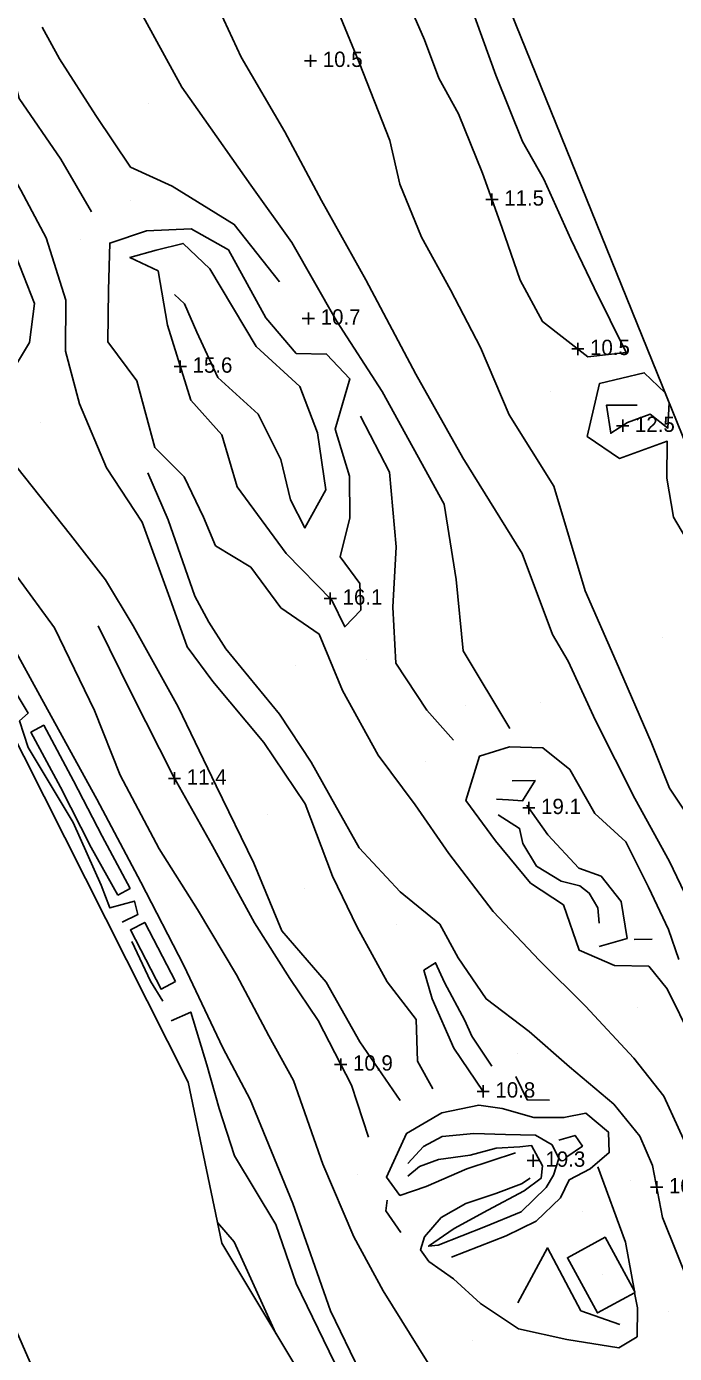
# Model space of a CAD drawing. Extents: x 2316231 to 2323598, y 363169 to 371906.
# Drawn here: x 2321145.5 to 2321357, y 370235.9 to 370669.2 of the extents above; entities that cross this region are included whole.
import ezdxf

# ---------------------------------------------------------------- set-up
doc = ezdxf.new("R2010")
doc.units = 0
for name, color, linetype in [('RD_DTM_BkLn1', 7, 'Continuous'), ('RD_DTM_Holes', 7, 'Continuous'), ('RD_DTM_Spot', 7, 'Continuous'), ('RD_DTM_TinHull', 7, 'Continuous'), ('RD_DTM_Void', 7, 'Continuous'), ('RD_EX_Road', 7, 'Continuous')]:
    doc.layers.add(name, color=color, linetype=linetype)

msp = doc.modelspace()

# ---------------------------------------------------------------- linework, layer by layer
at = {"layer": 'RD_DTM_BkLn1'}
for p, q in [((2321303.283, 370439.966), (2321287.994, 370465.333)), ((2321343.823, 370371.073), (2321349.76, 370371.225))]:
    msp.add_line(p, q, dxfattribs=at)
for points in [[(2321095.104, 370838.549), (2321106.9, 370830.963), (2321120.13, 370820.522), (2321134.171, 370806.445), (2321148.563, 370787.326), (2321155.431, 370774.673), (2321167.88, 370758.44), (2321178.411, 370739.764), (2321191.256, 370710.961), (2321204.225, 370683.754), (2321215.503, 370659.267), (2321229.851, 370634.787), (2321241.736, 370612.469), (2321256.273, 370586.516), (2321272.543, 370555.7), (2321287.931, 370528.428), (2321307.356, 370497.108), (2321317.191, 370470.678)], [(2321166.692, 370608.729), (2321156.687, 370625.95), (2321143.02, 370645.697), (2321139.377, 370659.675), (2321129.348, 370678.61), (2321116.078, 370701.328), (2321100.407, 370726.439), (2321084.462, 370753.707), (2321065.004, 370781.518), (2321049.856, 370800.449), (2321028.316, 370822.126), (2321001.341, 370834.458), (2320980.791, 370835.833)], [(2321154.64, 370472.869), (2321142.488, 370489.377), (2321128.682, 370513.676), (2321120.144, 370529.674), (2321109.083, 370544.963), (2321095.862, 370565.132), (2321084.807, 370586.293), (2321069.264, 370611.437), (2321056.818, 370634.294), (2321042.259, 370659.391), (2321027.715, 370688.401)], [(2321290.025, 370677.374), (2321298.704, 370653.383), (2321307.435, 370631.662), (2321314.33, 370619.356), (2321323.183, 370599.834), (2321330.83, 370583.917), (2321341.307, 370562.798), (2321328.747, 370561.407), (2321313.932, 370572.9), (2321306.601, 370586.427), (2321300.661, 370603.689), (2321294.368, 370621.361), (2321286.521, 370640.708), (2321280.081, 370652.371), (2321275.447, 370664.88), (2321267.471, 370683.198)], [(2321287.994, 370465.333), (2321285.707, 370488.607), (2321281.842, 370513.208), (2321261.585, 370550.085), (2321246.64, 370573.114), (2321232.11, 370598.708), (2321218.661, 370617.432), (2321201.444, 370642.041), (2321196.129, 370649.382), (2321181.681, 370675.913)], [(2321245.723, 370677.826), (2321254.102, 370657.475), (2321264.116, 370631.962), (2321267.396, 370617.699), (2321274.413, 370600.435), (2321283.909, 370583.244), (2321293.731, 370564.392), (2321303.026, 370542.421), (2321317.678, 370519.106), (2321327.827, 370484.903)], [(2321197.855, 370466.624), (2321192.255, 370482.578), (2321183.216, 370507.361), (2321171.573, 370525.124), (2321162.727, 370546.059), (2321158.187, 370563.164), (2321158.297, 370579.874), (2321151.818, 370600.223), (2321143.586, 370615.777), (2321131.818, 370636.402), (2321122.85, 370656.783), (2321113.172, 370672.46)], [(2321228.111, 370585.812), (2321213.298, 370604.623), (2321193.006, 370617.066), (2321179.443, 370623.25), (2321168.114, 370640.187), (2321156.203, 370658.672), (2321150.546, 370669.063)], [(2321241.043, 370470.832), (2321228.497, 370479.45), (2321218.754, 370492.673), (2321207.159, 370499.689), (2321203.213, 370508.969), (2321196.943, 370522.182), (2321187.395, 370531.708), (2321181.468, 370553.555), (2321172.043, 370566.299), (2321172.201, 370583.181), (2321172.641, 370598.508), (2321184.678, 370602.5), (2321199.174, 370603.171), (2321211.362, 370596.345), (2321223.607, 370574.138), (2321233.521, 370562.465), (2321243.432, 370562.292), (2321251.03, 370554.204), (2321246.268, 370537.751), (2321250.877, 370522.417), (2321251.062, 370508.842), (2321247.818, 370496.076), (2321254.307, 370487.307), (2321254.578, 370478.653), (2321249.367, 370473.219), (2321245.159, 370481.924), (2321230.218, 370497.135), (2321214.25, 370518.949), (2321209.186, 370535.875), (2321199.083, 370547.25), (2321191.463, 370571.69), (2321188.413, 370589.447), (2321179.193, 370593.804), (2321187.736, 370596.219), (2321196.6, 370598.398), (2321205.352, 370590.087), (2321220.442, 370564.787), (2321234.703, 370551.669), (2321240.463, 370536.598), (2321243.142, 370517.942), (2321236.347, 370505.522), (2321231.671, 370514.719), (2321228.492, 370527.857), (2321221.073, 370542.602), (2321207.931, 370554.571), (2321201.012, 370569.46), (2321197.042, 370578.682), (2321193.723, 370581.759)], [(2321140.891, 370597.039), (2321148.08, 370578.731), (2321146.423, 370566.002), (2321139.37, 370554.245)], [(2321363.467, 370497.534), (2321356.737, 370508.982), (2321354.515, 370521.761), (2321354.658, 370533.78), (2321339.103, 370528.201), (2321328.575, 370535.353), (2321332.549, 370552.65), (2321347.174, 370556.169), (2321354.016, 370549.609)], [(2321355.283, 370546.482), (2321354.91, 370538.096), (2321349.144, 370542.687), (2321341.754, 370539.886), (2321336.255, 370536.413), (2321334.856, 370545.614), (2321344.85, 370545.637)], [(2321266.031, 370461.336), (2321265.059, 370479.596), (2321266.192, 370499.349), (2321263.946, 370523.744), (2321254.533, 370541.988)], [(2321180.251, 370473.577), (2321171.221, 370488.569), (2321159.769, 370503.203), (2321142.254, 370525.384)], [(2321204.999, 370474.705), (2321200.382, 370483.25), (2321191.668, 370508.144), (2321185.031, 370523.435)], [(2321462.422, 370192.436), (2321464.032, 370206.907), (2321452.063, 370233.225), (2321443.112, 370248.747), (2321437.452, 370259.196), (2321435.091, 370275.485), (2321426.405, 370297.189), (2321414.04, 370318.191), (2321404.119, 370337.788), (2321394.56, 370357.878), (2321382.23, 370381.657), (2321370.16, 370398.51), (2321355.45, 370420.524), (2321349.442, 370435.572), (2321337.968, 370461.876), (2321327.827, 370484.903)], [(2321176.646, 370376.75), (2321181.841, 370379.299), (2321180.704, 370383.666), (2321172.667, 370381.401), (2321169.802, 370388.856), (2321160.706, 370409.303), (2321145.975, 370433.825), (2321143.173, 370442.55), (2321145.961, 370445.01), (2321137.174, 370459.689), (2321126.274, 370479.167)], [(2321373.342, 370054.777), (2321358.045, 370085.574), (2321345.881, 370110.926), (2321329.281, 370134.816), (2321317.006, 370155.874), (2321302.796, 370181.337), (2321289.265, 370207.662), (2321276.571, 370232.77), (2321261.937, 370256.391), (2321252.287, 370273.963), (2321242.184, 370297.777), (2321232.592, 370325.072), (2321224.625, 370339.623), (2321214.019, 370359.55), (2321201.24, 370380.869), (2321188.745, 370400.714), (2321176.047, 370424.799), (2321167.639, 370445.883), (2321154.64, 370472.869)], [(2321257.177, 370306.517), (2321251.526, 370323.519), (2321240.69, 370344.616), (2321231.381, 370358.341), (2321219.846, 370376.586), (2321206.174, 370401.698), (2321193.435, 370424.299), (2321179.794, 370451.231), (2321168.829, 370473.509)], [(2321267.476, 370318.496), (2321254.315, 370337.726), (2321243.258, 370357.194), (2321228.781, 370373.923), (2321219.693, 370395.978), (2321207.393, 370421.241), (2321195.018, 370447.055), (2321180.251, 370473.577)], [(2321406.892, 370255.712), (2321389.176, 370248.986), (2321375.672, 370248.197), (2321362.506, 370257.074), (2321353.097, 370280.277), (2321349.908, 370297.255), (2321345.727, 370306.876), (2321337.201, 370317.349), (2321322.792, 370329.492), (2321309.583, 370341.09), (2321295.526, 370351.68), (2321286.418, 370365.078), (2321280.401, 370376.057), (2321267.48, 370386.641), (2321254.059, 370400.994), (2321246.102, 370415.152), (2321238.378, 370429.027), (2321228.112, 370444.646), (2321210.578, 370466.034), (2321204.999, 370474.705)], [(2321362.947, 370299.429), (2321353.536, 370319.957), (2321343.715, 370332.314), (2321327.947, 370349.342), (2321312.933, 370364.231), (2321297.812, 370380.289), (2321283.368, 370399.188), (2321272.316, 370415.025), (2321260.332, 370431.271), (2321248.609, 370452.371), (2321241.043, 370470.832)], [(2321361.5, 370383.803), (2321355.413, 370396.614), (2321344.069, 370417.117), (2321331.253, 370442.562), (2321322.365, 370461.94), (2321317.191, 370470.678)], [(2321278.185, 370322.345), (2321273.103, 370331.362), (2321272.73, 370344.955), (2321263.246, 370357.277), (2321253.383, 370375.108), (2321245.415, 370391.762), (2321236.401, 370415.39), (2321222.952, 370435.442), (2321206.277, 370455.375), (2321197.855, 370466.624)], [(2321284.896, 370436.165), (2321276.153, 370446.033), (2321266.031, 370461.336)], [(2321358.473, 370364.528), (2321355.092, 370374.313), (2321348.549, 370388.194), (2321341.19, 370403.034), (2321331.061, 370412.211), (2321322.823, 370426.606), (2321314.056, 370433.731), (2321303.153, 370433.986), (2321293.369, 370430.92), (2321288.893, 370416.462), (2321298.609, 370403.33), (2321309.986, 370389.504), (2321320.822, 370382.392), (2321325.877, 370367.586), (2321337.499, 370362.639), (2321348.66, 370362.417), (2321354.605, 370354.991), (2321362.832, 370338.415)], [(2321298.911, 370416.908), (2321302.856, 370416.721), (2321307.418, 370416.406), (2321311.52, 370422.985), (2321304.078, 370422.954)], [(2321332.439, 370376.378), (2321331.992, 370381.473), (2321329.227, 370386.23), (2321326.113, 370388.651), (2321319.994, 370390.187), (2321311.935, 370395.093), (2321307.486, 370402.467), (2321306.464, 370407.384), (2321299.414, 370411.769)], [(2321308.828, 370414.983), (2321315.649, 370405.294), (2321325.793, 370394.419), (2321333.064, 370391.731), (2321339.589, 370383.516), (2321341.555, 370371.444), (2321332.414, 370368.779)], [(2321179.875, 370370.394), (2321185.985, 370357.538), (2321189.955, 370350.999)], [(2321294.56, 370321.479), (2321285.017, 370335.61), (2321277.889, 370351.675), (2321275.213, 370361.03), (2321279.048, 370363.507), (2321281.894, 370357.018), (2321288.601, 370344.597), (2321290.848, 370339.573), (2321297.388, 370329.772)], [(2321257.719, 370204.746), (2321249.591, 370225.56), (2321233.496, 370258.766), (2321226.834, 370278.021), (2321213.317, 370300.434), (2321208.401, 370315.915), (2321204.378, 370330.177), (2321199.099, 370347.391), (2321192.644, 370344.488)], [(2321316.186, 370318.609), (2321308.891, 370318.756), (2321305.195, 370326.396)], [(2321284.192, 370267.368), (2321302.032, 370274.296), (2321311.914, 370279.082), (2321319.82, 370286.789), (2321322.692, 370292.632), (2321329.488, 370296.23), (2321335.742, 370301.494), (2321335.448, 370308.218), (2321328.047, 370314.369), (2321320.925, 370312.954), (2321311.145, 370313.001), (2321300.738, 370315.952), (2321293.133, 370316.978)], [(2321270.021, 370293.775), (2321273.746, 370296.972), (2321279.962, 370299.258), (2321290.299, 370300.624), (2321298.821, 370302.966), (2321306.523, 370303.401), (2321310.381, 370303.82), (2321313.923, 370297.171), (2321313.465, 370293.126), (2321307.96, 370288.994), (2321296.114, 370282.666), (2321285.08, 370276.75), (2321276.745, 370270.945), (2321279.905, 370271.267), (2321295.302, 370277.409), (2321307.027, 370282.118), (2321315.182, 370290.06), (2321317.562, 370294.129), (2321319.275, 370299.573), (2321317.138, 370304.035), (2321311.679, 370307.209), (2321301.866, 370307.425), (2321291.503, 370307.756), (2321281.167, 370306.761), (2321275.093, 370303.53), (2321270.018, 370297.99)], [(2321321.908, 370300.078), (2321326.984, 370303.639), (2321324.561, 370307.102), (2321319.27, 370305.599)], [(2321267.706, 370275.429), (2321262.805, 370282.445), (2321263.261, 370285.995)], [(2321226.864, 370242.463), (2321224.094, 370248.447), (2321213.238, 370272.41), (2321207.768, 370278.66)], [(2321339.191, 370245.428), (2321326.51, 370249.862), (2321315.536, 370270.397), (2321305.861, 370252.458)]]:
    msp.add_lwpolyline(points, dxfattribs=at)
at = {"layer": 'RD_DTM_Holes'}
msp.add_lwpolyline([(2321261.802, 370184.289), (2321209.177, 370271.912), (2321198.19, 370324.497), (2321117.576, 370484.29), (2321037.89, 370459.753), (2321124.606, 370283.08), (2321175.43, 370167.171)], dxfattribs=at)
at = {"layer": 'RD_DTM_Spot'}
for p, q in [((2321185.317, 370644.252), (2321185.317, 370644.252)), ((2321179.337, 370612.273), (2321179.337, 370612.273)), ((2321163.077, 370599.557), (2321163.077, 370599.557)), ((2321237.501, 370573.891), (2321237.501, 370573.891)), ((2321316.532, 370549.902), (2321316.532, 370549.902)), ((2321150.061, 370539.968), (2321150.061, 370539.968)), ((2321353.192, 370469.559), (2321353.192, 370469.559)), ((2321233.283, 370460.721), (2321233.283, 370460.721)), ((2321256.582, 370462.426), (2321256.582, 370462.426)), ((2321288.695, 370447.579), (2321288.695, 370447.579)), ((2321313.374, 370448.506), (2321313.374, 370448.506)), ((2321275.734, 370429.116), (2321275.734, 370429.116)), ((2321319.258, 370416.911), (2321319.258, 370416.911)), ((2321224.008, 370411.987), (2321224.008, 370411.987)), ((2321236.279, 370387.804), (2321236.279, 370387.804)), ((2321266.135, 370375.867), (2321266.135, 370375.867)), ((2321345.054, 370348.821), (2321345.054, 370348.821)), ((2321305.872, 370333.744), (2321305.872, 370333.744)), ((2321253.554, 370294.237), (2321253.554, 370294.237)), ((2321342.667, 370292.333), (2321342.667, 370292.333)), ((2321326.959, 370282.359), (2321326.959, 370282.359)), ((2321333.458, 370261.666), (2321333.458, 370261.666)), ((2321355.174, 370249.589), (2321355.174, 370249.589)), ((2321291.132, 370240.31), (2321291.132, 370240.31))]:
    msp.add_line(p, q, dxfattribs=at)
at = {"layer": 'RD_DTM_TinHull'}
msp.add_lwpolyline([(2319782.271, 371232.132), (2319735.05, 371773.026), (2320925.274, 371905.831), (2321343.399, 371858.015), (2321109.741, 371125.092), (2321259.088, 370783.878), (2321451.866, 370308.131), (2321545.882, 369878.312), (2321496.483, 369600.925), (2321592.742, 369376.322), (2321772.553, 369180.585), (2321930.831, 369046.826), (2322410.389, 369187.058), (2322700.489, 369322.074), (2323031.423, 369488.086), (2323384.71, 369626.658), (2323598.112, 369182.404), (2323506.079, 369141.824), (2322749.057, 368805.183), (2322437.788, 368637.943)], dxfattribs=at)
at = {"layer": 'RD_DTM_Void'}
for p, q in [((2321238.197, 370656.027), (2321238.197, 370660.027)), ((2321236.197, 370658.027), (2321240.197, 370658.027)), ((2321295.436, 370612.745), (2321299.436, 370612.745)), ((2321297.436, 370610.745), (2321297.436, 370614.745)), ((2321237.501, 370571.891), (2321237.501, 370575.891)), ((2321235.501, 370573.891), (2321239.501, 370573.891)), ((2321323.47, 370563.95), (2321327.47, 370563.95)), ((2321325.47, 370561.95), (2321325.47, 370565.95)), ((2321195.673, 370556.186), (2321195.673, 370560.186)), ((2321193.673, 370558.186), (2321197.673, 370558.186)), ((2321338.126, 370538.858), (2321342.126, 370538.858)), ((2321340.126, 370536.858), (2321340.126, 370540.858)), ((2321242.653, 370482.438), (2321246.653, 370482.438)), ((2321244.653, 370480.438), (2321244.653, 370484.438)), ((2321193.78, 370421.69), (2321193.78, 370425.69)), ((2321191.78, 370423.69), (2321195.78, 370423.69)), ((2321309.481, 370412.055), (2321309.481, 370416.055)), ((2321307.481, 370414.055), (2321311.481, 370414.055)), ((2321246.051, 370330.285), (2321250.051, 370330.285)), ((2321248.051, 370328.285), (2321248.051, 370332.285)), ((2321292.56, 370321.479), (2321296.56, 370321.479)), ((2321294.56, 370319.479), (2321294.56, 370323.479)), ((2321308.908, 370298.883), (2321312.908, 370298.883)), ((2321310.908, 370296.883), (2321310.908, 370300.883)), ((2321349.235, 370290.189), (2321353.235, 370290.189)), ((2321351.235, 370288.189), (2321351.235, 370292.189))]:
    msp.add_line(p, q, dxfattribs=at)
at = {"layer": 'RD_EX_Road'}
for p, q in [((2321344.154, 370255.836), (2321343.94, 370256.229)), ((2321344.025, 370255.766), (2321344.154, 370255.836))]:
    msp.add_line(p, q, dxfattribs=at)
for points in [[(2321138.524, 370471.475), (2321152.33, 370446.25), (2321168.465, 370416.888), (2321182.791, 370389.794), (2321196.812, 370362.645), (2321209.553, 370335.683), (2321218.521, 370318.845), (2321232.443, 370284.941), (2321244.751, 370249.786), (2321254.411, 370229.808), (2321267.395, 370197.134), (2321276.195, 370173.462), (2321288.657, 370147.018), (2321306.408, 370116.906), (2321319.366, 370092.978), (2321331.773, 370066.68), (2321349.647, 370048.248), (2321365.863, 370037.715), (2321376.915, 370033.435)], [(2321175.25, 370385.547), (2321179.296, 370387.787), (2321170.127, 370404.862), (2321160.738, 370422.928), (2321151.08, 370441.062), (2321146.864, 370438.755), (2321156.569, 370420.846), (2321166.546, 370401.136), (2321175.25, 370385.547)], [(2321194.089, 370357.353), (2321184.082, 370376.667), (2321179.399, 370374.241), (2321189.406, 370354.927), (2321194.089, 370357.353)], [(2321305.12, 370301.474), (2321289.21, 370296.166), (2321275.974, 370290.486), (2321267.36, 370287.549), (2321262.96, 370293.528), (2321269.515, 370307.75), (2321281.115, 370314.462), (2321293.133, 370316.978)], [(2321332.01, 370296.904), (2321341.029, 370272.219), (2321343.94, 370256.229)], [(2321344.025, 370255.766), (2321344.917, 370250.864), (2321344.848, 370241.365), (2321338.896, 370237.797), (2321321.889, 370240.509), (2321306.09, 370244.003), (2321293.741, 370252.247), (2321284.933, 370260.282), (2321276.8, 370265.998), (2321274.12, 370269.811), (2321275.377, 370273.953), (2321280.871, 370280.368), (2321288.874, 370284.848), (2321298.67, 370288.207), (2321307.038, 370291.347), (2321309.879, 370293.121)], [(2321343.94, 370256.229), (2321334.357, 370273.851), (2321322.097, 370267.184), (2321331.894, 370249.169), (2321344.025, 370255.766)]]:
    msp.add_lwpolyline(points, dxfattribs=at)

# ---------------------------------------------------------------- texts
at = {"layer": 'RD_DTM_Void'}
for s, p in [('10.5', (2321242.197, 370656.027)), ('11.5', (2321301.436, 370610.745)), ('10.7', (2321241.501, 370571.891)), ('10.5', (2321329.47, 370561.95)), ('15.6', (2321199.673, 370556.186)), ('12.5', (2321344.126, 370536.858)), ('16.1', (2321248.653, 370480.438)), ('11.4', (2321197.78, 370421.69)), ('19.1', (2321313.481, 370412.055)), ('10.9', (2321252.051, 370328.285)), ('10.8', (2321298.56, 370319.479)), ('19.3', (2321314.908, 370296.883)), ('10.7', (2321355.235, 370288.189))]:
    msp.add_text(s, height=5, dxfattribs=at).set_placement(p)

doc.saveas('drawing.dxf')
